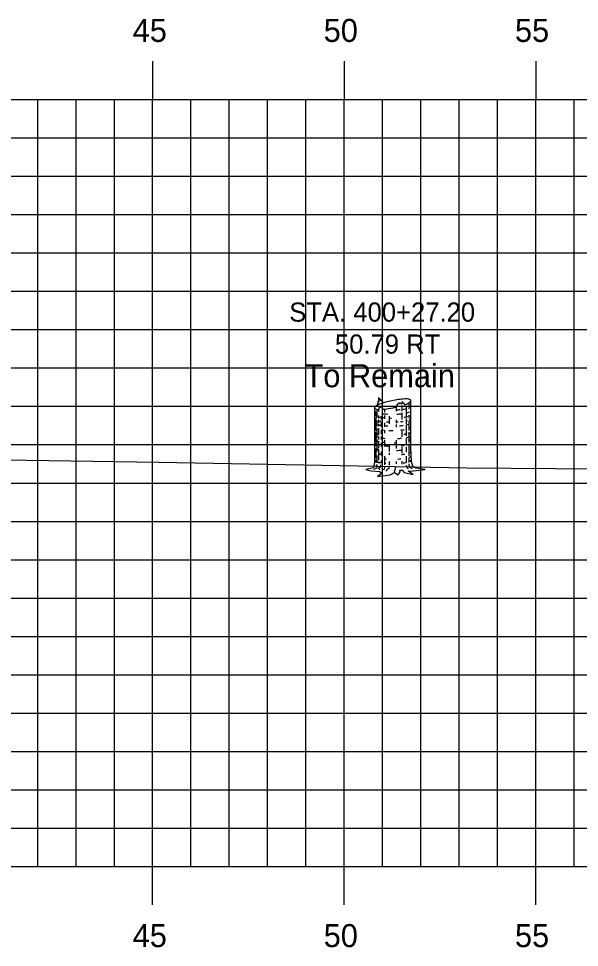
# Model space of a CAD drawing. Extents: x -161 to 764, y 111 to 210.
# Drawn here: x -46.19 to -31.55, y 176.32 to 200.54 of the extents above; entities that cross this region are included whole.
import ezdxf

# ---------------------------------------------------------------- set-up
doc = ezdxf.new("R2010")
doc.units = 0
for name, color, linetype in [('D_Text_Monospaced', 7, 'Continuous'), ('D_Text_Standard', 7, 'Continuous'), ('H_V ANNOTATION', 7, 'Continuous'), ('MAJOR', 7, 'Continuous'), ('MINOR', 7, 'Continuous'), ('S_Roadway_Centerline', 7, 'Continuous'), ('S_Trees_Decid_NonPay', 7, 'Continuous')]:
    doc.layers.add(name, color=color, linetype=linetype)

msp = doc.modelspace()

# ---------------------------------------------------------------- linework, layer by layer
at = {"layer": 'MAJOR'}
for p, q in [((-42.693, 199.435), (-42.693, 198.433)), ((-37.693, 199.435), (-37.693, 198.433)), ((-32.693, 199.435), (-32.693, 198.433)), ((-157.693, 198.433), (-17.693, 198.433)), ((-157.693, 198.433), (-17.693, 198.433)), ((-42.693, 178.433), (-42.693, 198.433)), ((-37.693, 178.433), (-37.693, 198.433)), ((-32.693, 178.433), (-32.693, 198.433)), ((-157.693, 193.433), (-17.693, 193.433)), ((-157.693, 188.433), (-17.693, 188.433)), ((-157.693, 183.433), (-17.693, 183.433)), ((-157.693, 178.433), (-17.693, 178.433)), ((-157.693, 178.433), (-17.693, 178.433)), ((-42.693, 177.431), (-42.693, 178.433)), ((-37.693, 177.431), (-37.693, 178.433)), ((-32.693, 177.431), (-32.693, 178.433))]:
    msp.add_line(p, q, dxfattribs=at)
at = {"layer": 'MINOR'}
for p, q in [((-45.693, 178.433), (-45.693, 198.433)), ((-44.693, 178.433), (-44.693, 198.433)), ((-43.693, 178.433), (-43.693, 198.433)), ((-41.693, 178.433), (-41.693, 198.433)), ((-40.693, 178.433), (-40.693, 198.433)), ((-39.693, 178.433), (-39.693, 198.433)), ((-38.693, 178.433), (-38.693, 198.433)), ((-36.693, 178.433), (-36.693, 198.433)), ((-35.693, 178.433), (-35.693, 198.433)), ((-34.693, 178.433), (-34.693, 198.433)), ((-33.693, 178.433), (-33.693, 198.433)), ((-31.693, 178.433), (-31.693, 198.433)), ((-157.693, 197.433), (-17.693, 197.433)), ((-157.693, 196.433), (-17.693, 196.433)), ((-157.693, 195.433), (-17.693, 195.433)), ((-157.693, 194.433), (-17.693, 194.433)), ((-157.693, 192.433), (-17.693, 192.433)), ((-157.693, 191.433), (-17.693, 191.433)), ((-157.693, 190.433), (-17.693, 190.433)), ((-157.693, 189.433), (-17.693, 189.433)), ((-157.693, 187.433), (-17.693, 187.433)), ((-157.693, 186.433), (-17.693, 186.433)), ((-157.693, 185.433), (-17.693, 185.433)), ((-157.693, 184.433), (-17.693, 184.433)), ((-157.693, 182.433), (-17.693, 182.433)), ((-157.693, 181.433), (-17.693, 181.433)), ((-157.693, 180.433), (-17.693, 180.433)), ((-157.693, 179.433), (-17.693, 179.433))]:
    msp.add_line(p, q, dxfattribs=at)
at = {"layer": 'S_Roadway_Centerline'}
msp.add_lwpolyline([(-157.693, 186.896), (-152.22, 186.735), (-150.498, 186.807), (-148.901, 186.975), (-141.893, 187.734), (-139.882, 188.09), (-132.124, 189.256), (-128.171, 189.315), (-121.467, 188.992), (-115.974, 188.872), (-110.769, 188.6), (-96.239, 188.433), (-93.99, 188.538), (-87.1, 188.918), (-86.065, 188.968), (-75.289, 189.172), (-68.973, 189.373), (-42.532, 188.98), (-34.493, 188.828), (-32.191, 188.81), (-29.47, 188.805), (-17.693, 188.431)], dxfattribs=at)
at = {"layer": 'S_Trees_Decid_NonPay'}
for p, q in [((-36.838, 190.354), (-36.838, 190.136)), ((-36.638, 190.359), (-36.638, 190.28)), ((-36.341, 190.412), (-36.341, 190.305)), ((-36.194, 190.457), (-36.194, 190.309)), ((-36.075, 190.44), (-36.075, 190.14)), ((-36.007, 190.527), (-36.007, 190.433)), ((-36.865, 190.284), (-36.865, 190.202)), ((-36.865, 190.132), (-36.865, 190.002)), ((-36.796, 190.349), (-36.796, 190.297)), ((-36.796, 190.194), (-36.796, 190.111)), ((-36.725, 190.175), (-36.725, 190.089)), ((-36.638, 190.194), (-36.638, 190.109)), ((-36.521, 190.175), (-36.521, 189.975)), ((-36.194, 190.261), (-36.194, 190.093)), ((-36.075, 190.111), (-36.075, 189.98)), ((-36.007, 190.206), (-36.007, 190.124)), ((-36.865, 189.98), (-36.865, 189.798)), ((-36.838, 190.067), (-36.838, 189.915)), ((-36.796, 190.076), (-36.796, 190.002)), ((-36.796, 189.975), (-36.796, 189.915)), ((-36.725, 190.019), (-36.725, 189.897)), ((-36.638, 189.998), (-36.638, 189.897)), ((-36.341, 190.076), (-36.341, 189.99)), ((-36.341, 189.955), (-36.341, 189.885)), ((-36.075, 189.946), (-36.075, 189.665)), ((-36.007, 190.054), (-36.007, 189.803)), ((-36.865, 189.751), (-36.865, 189.504)), ((-36.838, 189.811), (-36.838, 189.732)), ((-36.838, 189.706), (-36.838, 189.599)), ((-36.796, 189.862), (-36.796, 189.681)), ((-36.796, 189.65), (-36.796, 189.568)), ((-36.725, 189.822), (-36.725, 189.707)), ((-36.725, 189.646), (-36.725, 189.564)), ((-36.638, 189.812), (-36.638, 189.736)), ((-36.194, 189.786), (-36.194, 189.638)), ((-36.007, 189.72), (-36.007, 189.49)), ((-36.865, 189.485), (-36.865, 189.391)), ((-36.838, 189.564), (-36.838, 189.463)), ((-36.838, 189.437), (-36.838, 189.255)), ((-36.796, 189.514), (-36.796, 189.343)), ((-36.725, 189.477), (-36.725, 189.38)), ((-36.638, 189.551), (-36.638, 189.454)), ((-36.521, 189.438), (-36.521, 189.251)), ((-36.341, 189.551), (-36.341, 189.329)), ((-36.075, 189.595), (-36.075, 189.45)), ((-36.007, 189.419), (-36.007, 189.259)), ((-36.867, 189.337), (-36.866, 189.078)), ((-36.838, 189.152), (-36.838, 188.96)), ((-36.796, 189.31), (-36.796, 189.03)), ((-36.725, 189.251), (-36.725, 189.152)), ((-36.521, 189.22), (-36.521, 189.167)), ((-36.194, 189.368), (-36.194, 189.215)), ((-36.075, 189.38), (-36.075, 189.238)), ((-36.007, 189.242), (-36.007, 189.137)), ((-36.837, 188.913), (-36.871, 188.862)), ((-36.865, 189.039), (-36.865, 188.965)), ((-36.796, 188.978), (-36.796, 188.952)), ((-36.725, 189.022), (-36.725, 188.964)), ((-36.638, 189.129), (-36.638, 188.905)), ((-36.521, 188.991), (-36.521, 188.9)), ((-36.341, 188.996), (-36.341, 188.929)), ((-36.194, 189.003), (-36.194, 188.925)), ((-36.075, 189.137), (-36.075, 188.956)), ((-36.075, 188.896), (-36.033, 188.8)), ((-36.007, 189.101), (-36.007, 188.977)), ((-36.919, 188.791), (-36.851, 188.822)), ((-36.381, 188.709), (-36.346, 188.855))]:
    msp.add_line(p, q, dxfattribs=at)
for points in [[(-36.812, 190.472), (-36.808, 190.566), (-36.793, 190.54), (-36.793, 190.661), (-36.772, 190.597), (-36.758, 190.63), (-36.741, 190.574), (-36.725, 190.591), (-36.707, 190.583), (-36.688, 190.516)], [(-36.907, 190.391), (-36.907, 188.979), (-36.929, 188.831), (-37.132, 188.788), (-36.993, 188.752), (-36.774, 188.734), (-36.705, 188.69), (-36.826, 188.602), (-36.495, 188.645), (-36.381, 188.709), (-36.289, 188.649), (-36.233, 188.728), (-36.241, 188.765), (-36.18, 188.767), (-36.128, 188.709), (-35.896, 188.658), (-36.023, 188.746), (-35.891, 188.748), (-35.583, 188.786), (-35.821, 188.816), (-35.899, 188.874), (-35.938, 188.996), (-35.955, 189.349), (-35.955, 190.583)], [(-36.789, 190.348), (-36.772, 190.41), (-36.75, 190.398), (-36.719, 190.433), (-36.686, 190.354)], [(-36.319, 190.417), (-36.311, 190.484), (-36.287, 190.488), (-36.278, 190.523), (-36.247, 190.509), (-36.233, 190.523), (-36.209, 190.5), (-36.186, 190.509), (-36.173, 190.558), (-36.165, 190.515), (-36.134, 190.523), (-36.131, 190.472)], [(-36.789, 188.822), (-36.745, 188.857), (-36.737, 188.905)], [(-36.004, 188.934), (-35.996, 188.857), (-35.918, 188.808)], [(-36.867, 188.839), (-36.789, 188.822), (-36.772, 188.779)], [(-36.641, 188.857), (-36.647, 188.788), (-36.711, 188.775)], [(-36.529, 188.851), (-36.529, 188.814), (-36.581, 188.784), (-36.598, 188.734)]]:
    msp.add_lwpolyline(points, dxfattribs=at)
for centre, radius, start, end in [((-35.936, 188.125), 2.507, 93.9457, 101.8277), ((-36.087, 190.304), 0.322, 71.8277, 93.9457), ((-36.015, 190.521), 0.0935, 60.604, 71.8277), ((-35.986, 190.574), 0.0336, 41.8277, 60.604), ((-35.979, 190.58), 0.0237, 27.8832, 41.8277), ((-36.883, 190.391), 0.0237, 161.8277, 175.7722), ((-36.888, 190.391), 0.0179, 175.7722, 191.8277), ((-36.888, 190.391), 0.0179, 191.8277, 207.8832), ((-36.873, 190.388), 0.0336, 143.0514, 161.8277), ((-36.883, 190.394), 0.0237, 207.8832, 221.8277), ((-36.876, 190.401), 0.0336, 221.8277, 240.604), ((-36.825, 190.352), 0.0935, 131.8277, 143.0514), ((-36.847, 190.453), 0.0935, 240.604, 251.8277), ((-36.673, 190.182), 0.322, 109.7098, 131.8277), ((-36.775, 190.67), 0.322, 251.8277, 267.5521), ((-35.936, 188.125), 2.507, 101.8277, 109.7098), ((-36.926, 192.85), 2.507, 275.4987, 281.8277), ((-36.926, 192.85), 2.507, 281.8277, 284.0013), ((-36.43, 192.697), 2.356, 276.7201, 278.1032), ((-36.926, 192.85), 2.507, 288.4719, 289.7098), ((-36.144, 190.687), 0.326, 278.1032, 282.1964), ((-36.189, 190.793), 0.322, 289.7098, 311.8277), ((-36.144, 190.687), 0.326, 291.6757, 300), ((-36.03, 190.49), 0.0984, 300, 311.2506), ((-36.037, 190.622), 0.0935, 311.8277, 323.0514), ((-35.989, 190.442), 0.0356, 311.2506, 330), ((-35.989, 190.586), 0.0336, 323.0514, 341.8277), ((-35.973, 190.583), 0.0179, 11.8277, 27.8832), ((-35.98, 190.437), 0.0252, 330, 343.9485), ((-35.979, 190.583), 0.0237, 341.8277, 355.7722), ((-35.973, 190.583), 0.0179, 355.7722, 11.8277), ((-35.974, 190.435), 0.0191, 360, 16.0515), ((-35.974, 190.435), 0.0191, 343.9485, 360), ((-36.887, 190.322), 0.0191, 173.8872, 180), ((-36.887, 190.322), 0.0191, 180, 196.0515), ((-36.887, 190.221), 0.0191, 173.8872, 180), ((-36.887, 190.221), 0.0191, 180, 196.0515), ((-36.887, 190.118), 0.0191, 173.8872, 180), ((-36.887, 190.118), 0.0191, 180, 196.0515), ((-36.881, 190.324), 0.0252, 196.0515, 210), ((-36.881, 190.223), 0.0252, 196.0515, 210), ((-36.872, 190.329), 0.0356, 210, 228.7494), ((-36.872, 190.228), 0.0356, 210, 228.7494), ((-36.83, 190.376), 0.0984, 228.7494, 240), ((-36.83, 190.275), 0.0984, 228.7494, 240), ((-36.716, 190.574), 0.326, 240, 248.0494), ((-36.716, 190.473), 0.326, 240, 248.0494), ((-36.716, 190.473), 0.326, 260.9146, 261.8968), ((-36.43, 192.483), 2.356, 261.8968, 264.9353), ((-36.43, 192.584), 2.356, 263.2266, 266.8519), ((-36.43, 192.483), 2.356, 267.8019, 269.1881), ((-36.43, 192.697), 2.356, 272.1614, 274.76), ((-36.43, 192.584), 2.356, 272.6327, 275.758), ((-36.43, 192.483), 2.356, 277.4481, 278.1032), ((-36.144, 190.473), 0.326, 278.1032, 289.5833), ((-36.144, 190.574), 0.326, 282.1964, 299.0901), ((-36.144, 190.473), 0.326, 296.4281, 300), ((-36.03, 190.275), 0.0984, 300, 311.2506), ((-35.989, 190.228), 0.0356, 311.2506, 330), ((-35.989, 190.125), 0.0356, 311.2506, 330), ((-35.98, 190.223), 0.0252, 330, 343.9485), ((-35.98, 190.12), 0.0252, 330, 343.9485), ((-35.974, 190.221), 0.0191, 360, 16.0515), ((-35.974, 190.221), 0.0191, 343.9485, 360), ((-35.974, 190.118), 0.0191, 360, 16.0515), ((-35.974, 190.118), 0.0191, 343.9485, 360), ((-36.887, 190.013), 0.0191, 173.8872, 180), ((-36.887, 190.013), 0.0191, 180, 196.0515), ((-36.887, 189.898), 0.0191, 173.8872, 180), ((-36.887, 189.898), 0.0191, 180, 196.0515), ((-36.881, 190.015), 0.0252, 196.0515, 210), ((-36.881, 189.9), 0.0252, 196.0515, 210), ((-36.872, 190.02), 0.0356, 210, 228.7494), ((-36.872, 189.905), 0.0356, 210, 228.7494), ((-36.83, 190.068), 0.0984, 228.7494, 240), ((-36.83, 189.952), 0.0984, 228.7494, 240), ((-36.716, 190.265), 0.326, 240, 248.0494), ((-36.716, 190.15), 0.326, 240, 255.9618), ((-36.716, 190.37), 0.326, 255.9618, 261.8968), ((-36.716, 190.265), 0.326, 255.9618, 261.8968), ((-36.43, 192.38), 2.356, 261.8968, 262.6162), ((-36.43, 192.275), 2.356, 261.8968, 262.8131), ((-36.43, 192.275), 2.356, 264.9353, 266.9933), ((-36.43, 192.38), 2.356, 266.0259, 267.8019), ((-36.43, 192.38), 2.356, 272.1614, 273.4964), ((-36.43, 192.275), 2.356, 274.3638, 276.7318), ((-36.43, 192.38), 2.356, 275.0054, 276.6587), ((-36.144, 190.37), 0.326, 282.1964, 288.3169), ((-36.144, 190.265), 0.326, 282.1964, 294.8455), ((-36.144, 190.15), 0.326, 294.8455, 300), ((-36.144, 190.37), 0.326, 296.757, 300), ((-36.03, 190.173), 0.0984, 300, 311.2506), ((-36.03, 189.952), 0.0984, 300, 311.2506), ((-35.989, 189.905), 0.0356, 311.2506, 330), ((-35.98, 189.9), 0.0252, 330, 343.9485), ((-35.974, 189.898), 0.0191, 360, 16.0515), ((-35.974, 189.898), 0.0191, 343.9485, 360), ((-36.887, 189.784), 0.0191, 173.8872, 180), ((-36.887, 189.784), 0.0191, 180, 196.0515), ((-36.881, 189.786), 0.0252, 196.0515, 210), ((-36.872, 189.791), 0.0356, 210, 228.7494), ((-36.884, 189.684), 0.0191, 173.8872, 180), ((-36.884, 189.684), 0.0191, 180, 196.0515), ((-36.878, 189.685), 0.0252, 196.0515, 210), ((-36.869, 189.691), 0.0356, 210, 228.7494), ((-36.831, 189.838), 0.0984, 228.7494, 240), ((-36.828, 189.738), 0.0984, 228.7494, 240), ((-36.717, 190.035), 0.326, 240, 242.9942), ((-36.714, 189.935), 0.326, 240, 247.5951), ((-36.717, 190.035), 0.326, 248.1902, 256.0964), ((-36.43, 192.16), 2.356, 262.8131, 264.9353), ((-36.43, 192.16), 2.356, 267.586, 270), ((-36.43, 192.16), 2.356, 270, 270.4422), ((-36.43, 192.16), 2.356, 275.2089, 277.3412), ((-36.431, 192.045), 2.356, 277.1385, 278.1032), ((-36.145, 190.035), 0.326, 278.1032, 282.3301), ((-36.142, 189.935), 0.326, 283.0921, 300), ((-36.145, 190.035), 0.326, 292.1344, 300), ((-36.031, 189.838), 0.0984, 300, 311.2506), ((-35.99, 189.791), 0.0356, 311.2506, 330), ((-35.981, 189.786), 0.0252, 330, 343.9485), ((-35.975, 189.784), 0.0191, 360, 16.0515), ((-35.975, 189.784), 0.0191, 343.9485, 360), ((-35.971, 189.684), 0.0191, 360, 16.0515), ((-36.887, 189.579), 0.0191, 173.8872, 180), ((-36.887, 189.579), 0.0191, 180, 196.0515), ((-36.887, 189.488), 0.0191, 173.8872, 180), ((-36.881, 189.581), 0.0252, 196.0515, 210), ((-36.872, 189.586), 0.0356, 210, 228.7494), ((-36.83, 189.633), 0.0984, 228.7494, 240), ((-36.716, 189.83), 0.326, 240, 242.8475), ((-36.716, 189.83), 0.326, 248.0494, 255.9618), ((-36.428, 191.945), 2.356, 262.7545, 265.0266), ((-36.43, 191.84), 2.356, 263.572, 264.9353), ((-36.43, 191.75), 2.356, 264.7274, 267.8019), ((-36.43, 191.84), 2.356, 270.9946, 272.1614), ((-36.428, 191.945), 2.356, 273.1471, 275.6557), ((-36.43, 191.75), 2.356, 275.5135, 277.4157), ((-36.144, 189.74), 0.326, 286.0817, 298.061), ((-36.144, 189.83), 0.326, 294.8455, 300), ((-36.03, 189.633), 0.0984, 300, 311.2506), ((-35.989, 189.586), 0.0356, 311.2506, 330), ((-35.98, 189.581), 0.0252, 330, 343.9485), ((-35.974, 189.579), 0.0191, 360, 16.0515), ((-35.974, 189.579), 0.0191, 343.9485, 360), ((-36.883, 189.26), 0.0191, 173.8872, 180), ((-36.883, 189.26), 0.0191, 180, 196.0515), ((-36.877, 189.262), 0.0252, 196.0515, 210), ((-36.868, 189.267), 0.0356, 210, 228.7494), ((-36.826, 189.314), 0.0984, 228.7494, 240), ((-36.716, 189.626), 0.326, 248.0494, 255.9618), ((-36.712, 189.511), 0.326, 255.2259, 261.8968), ((-36.426, 191.521), 2.356, 261.8968, 262.7137), ((-36.43, 191.636), 2.356, 272.531, 275.758), ((-36.426, 191.521), 2.356, 275.5148, 277.7774), ((-36.14, 189.511), 0.326, 294.0625, 300), ((-36.026, 189.314), 0.0984, 300, 311.2506), ((-35.985, 189.267), 0.0356, 311.2506, 330), ((-35.98, 189.156), 0.0356, 311.2506, 330), ((-35.976, 189.262), 0.0252, 330, 343.9485), ((-35.97, 189.26), 0.0191, 360, 16.0515), ((-35.97, 189.26), 0.0191, 343.9485, 360), ((-35.971, 189.151), 0.0252, 330, 343.9485), ((-35.965, 189.149), 0.0191, 360, 16.0515), ((-35.965, 189.149), 0.0191, 343.9485, 360), ((-36.872, 189.039), 0.0191, 173.8872, 180), ((-36.872, 189.039), 0.0191, 180, 196.0515), ((-36.866, 189.041), 0.0252, 196.0515, 210), ((-36.857, 189.046), 0.0356, 210, 228.7494), ((-36.816, 189.093), 0.0984, 228.7494, 240), ((-36.707, 189.401), 0.326, 240, 246.3456), ((-36.702, 189.29), 0.326, 245.2906, 261.8968), ((-36.416, 191.3), 2.356, 261.8968, 262.4597), ((-36.421, 191.411), 2.356, 264.7171, 265.8136), ((-36.416, 191.3), 2.356, 264.5833, 265.4449), ((-36.421, 191.411), 2.356, 273.1842, 275.0911), ((-36.416, 191.3), 2.356, 276.4667, 278.1032), ((-36.13, 189.29), 0.326, 278.1032, 279.6166), ((-36.13, 189.29), 0.326, 292.0839, 300), ((-36.135, 189.401), 0.326, 298.0903, 300), ((-36.021, 189.203), 0.0984, 300, 311.2506), ((-36.016, 189.093), 0.0984, 300, 311.2506), ((-35.974, 189.046), 0.0356, 311.2506, 330), ((-35.965, 189.041), 0.0252, 330, 343.9485), ((-35.959, 189.039), 0.0191, 360, 16.0515), ((-35.959, 189.039), 0.0191, 343.9485, 360)]:
    msp.add_arc(centre, radius, start, end, dxfattribs=at)

# ---------------------------------------------------------------- texts
at = {"layer": 'D_Text_Monospaced'}
for s, height, p in [('STA. 400+27.20', 0.49998, (-39.128, 192.64)), ('50.79 RT', 0.5, (-37.936, 191.806))]:
    msp.add_text(s, height=height, dxfattribs=at).set_placement(p)
at = {"layer": 'D_Text_Standard'}
msp.add_text('To Remain', height=0.6, dxfattribs=at).set_placement((-38.729, 190.93))
at = {"layer": 'H_V ANNOTATION'}
for s, p in [('45', (-43.215, 199.933)), ('50', (-38.229, 199.933)), ('55', (-33.237, 199.933)), ('45', (-43.215, 176.333)), ('50', (-38.229, 176.333)), ('55', (-33.237, 176.333))]:
    msp.add_text(s, height=0.6, rotation=360, dxfattribs=at).set_placement(p)

doc.saveas('drawing.dxf')
